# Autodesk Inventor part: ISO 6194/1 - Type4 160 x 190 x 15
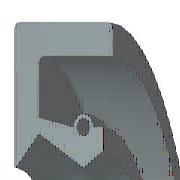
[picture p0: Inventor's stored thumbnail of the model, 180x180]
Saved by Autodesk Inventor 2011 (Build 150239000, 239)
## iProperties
Created: 2010-02
Part Number: ISO 6194/1 - Type4 160 x 190 x 15
Material: Rubber
Description: Rotary shaft lip type seals
Document SubType Name: Modeling
Standard: ISO 6194/1
Designer: 129877
Standard Revision: First edition 1984-11-15
Standards Organization: ISO
Language: en-US
Size Designation: Type4 160 x 190 x 15
Categories: <MemberInstance><Categories><Category DisplayName="Shaft Parts" InternalName="7f7aeb1f-a693-4053-b835-cee3144e0d98" Mnemonic="SHFT"><Category DisplayName="Seali
Density: 0.93 g/cm^3
Mass: 65.3692 g
Surface Area: 443.033 cm^2
Volume: 70.2894 cm^3
IsCustomPart: 0
Author: 129877
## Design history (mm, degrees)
revolve "Body" stored, may be unused: angle "d17" = 90 deg
revolve "Spring1" stored, may be unused: angle "d18" = 90 deg
body "Solid1"
sketch "Sketch1"
  geometry: L1 (0, 95)-(15, 95); L2 (15, 91.25)-(3.75, 91.25); L3 (3.75, 83.75)-(10.5, 80); L4 (10.5, 80)-(0, 80); L5 (0, 0)-(9.586, 0) reference; L6 (10.5, 80)-(13.5, 81.875); L7 (0, 18)-(0, -3) reference; L8 (-1.941, 0)-(11.507, 0) reference; L9 (9, 84.5)-(3.75, 85.55); L10 (3.75, 85.55)-(3.75, 91.25); L11 (0, 95)-(0, 80.188); L12 (10.5, 80)-(0, 80); L13 (3.75, 83.75)-(0.325, 80.06); L14 (15, 95)-(15, 91.25); L15 (12, 84.5)-(13.5, 84.5); L16 (13.5, 84.5)-(13.5, 81.875); C1 r 0.975 at (10.5, 84.5); A1 r 1.5 centre (10.5, 84.5) between (12, 84.5) and (9, 84.5); A2 r 0.188 centre (0.187, 80.188) between (0, 80.188) and (0.325, 80.06); 1 further point
  constraints: 28 end point, 5 horizontal alignment, 5 point on line, 4 point on circle, 4 vertical alignment, 3 centre point, 3 tangent, 2 collinear, 2 horizontal, 2 perpendicular, 1 coincident, 1 parallel
  dimensions: "d0" = 190 diameter of L1 L5 (= SD2); "d1" = 3.75 distance of L1.end L2.start (= SD); "d2" = 1.95 diameter of C1 (= SPDI); "d3" = 3 diameter of A1 (= SPDA); "d4" = 160 diameter of L3.end L5 (= NND); "d5" = 167.5 diameter of L3.start L5 (= TKDM); "d7" = 171.1 diameter of L9.end L5 (= TKDM + 0.24 x SWDT); "d8" = 3.75 distance between parallel lines of L11 L10 (= SD); "d9" = 10.5 distance from line of L11 C1.centre (= SPDST); "d10" = 169 diameter of C1.centre L5 (= HLDM); "d11" = 0.1875 radius of A2 (= 0.25 x LAB); "d12" = 13.5 distance between parallel lines of L11 L16 (= SDI); "d13" = 163.75 diameter of L6.end L5 (= ABDM); "d14" = 15 distance from line of L11 L1.end (= SWDT)
fillet "Fillet1" dims "d6" = 1 (= RR)
other parameters: "SD2" = 190 [user parameter; used in 1 equation term], "SWDT" = 15 [user parameter; used in 2 equation terms], "RR" = 1 [user parameter; used in 1 equation term], "SD" = 3.75 [user parameter; used in 2 equation terms], "NND" = 160 [user parameter; used in 1 equation term], "SPDA" = 3 [user parameter; used in 1 equation term], "SPDI" = 1.95 [user parameter; used in 1 equation term], "TKDM" = 167.5 [user parameter; used in 2 equation terms], "HLDM" = 169 [user parameter; used in 1 equation term], "ABDM" = 163.75 [user parameter; used in 1 equation term], "SDI" = 13.5 [user parameter; used in 1 equation term], "SPDST" = 10.5 [user parameter; used in 1 equation term], "LAB" = 0.75 [user parameter; used in 1 equation term], "d15" = 0, "d16" = 0, "d19" = 0
